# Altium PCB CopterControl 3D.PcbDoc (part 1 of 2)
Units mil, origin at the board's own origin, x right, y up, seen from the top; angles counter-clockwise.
Board outline 1417.32 x 1417.32 mil, 2 copper layers (Top Layer, Bottom Layer), stack 61.2 mil thick; 64 components, 58 nets, 262 pads, 81 vias.
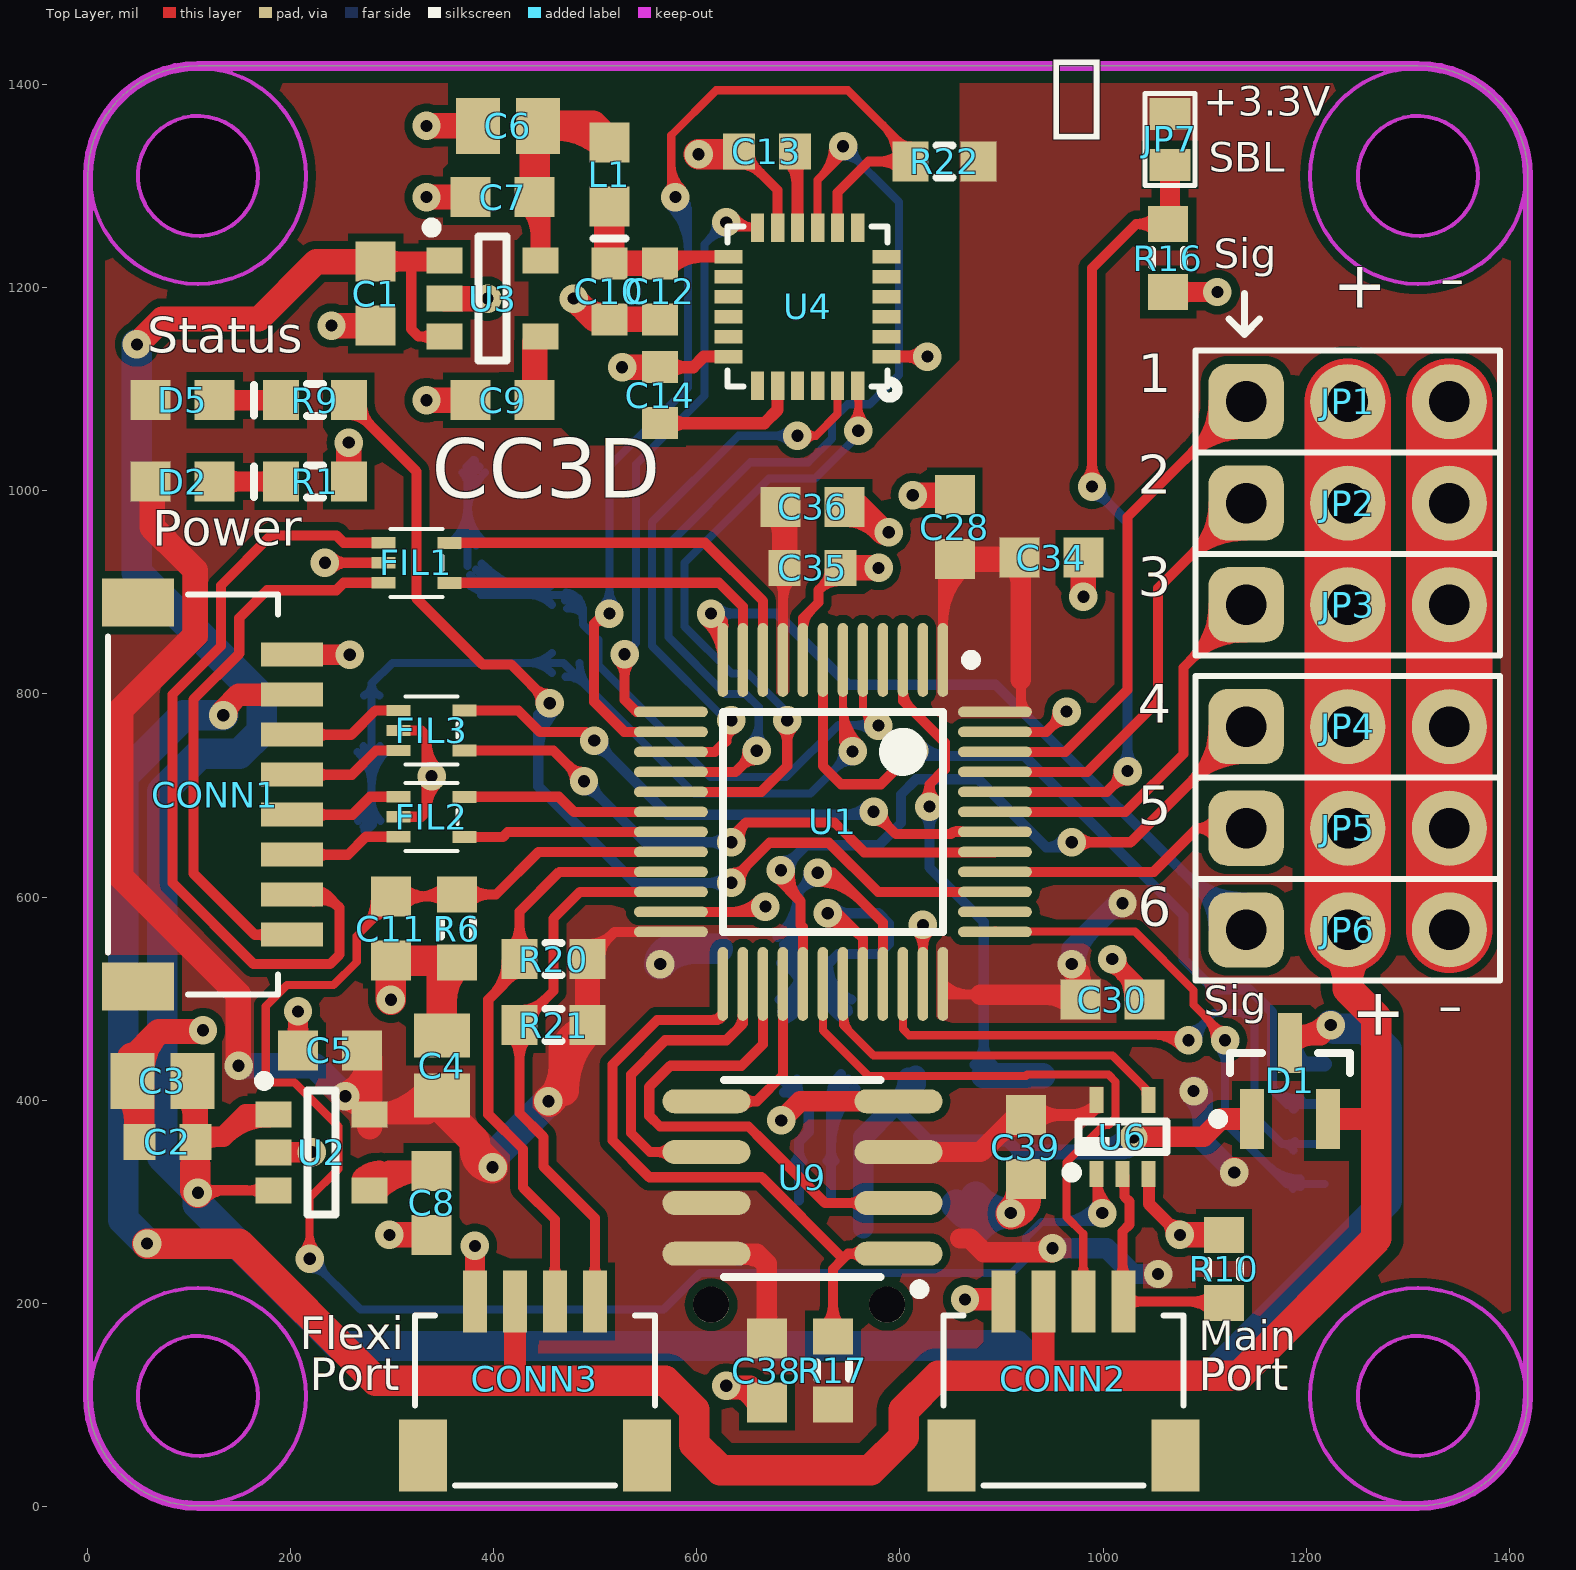
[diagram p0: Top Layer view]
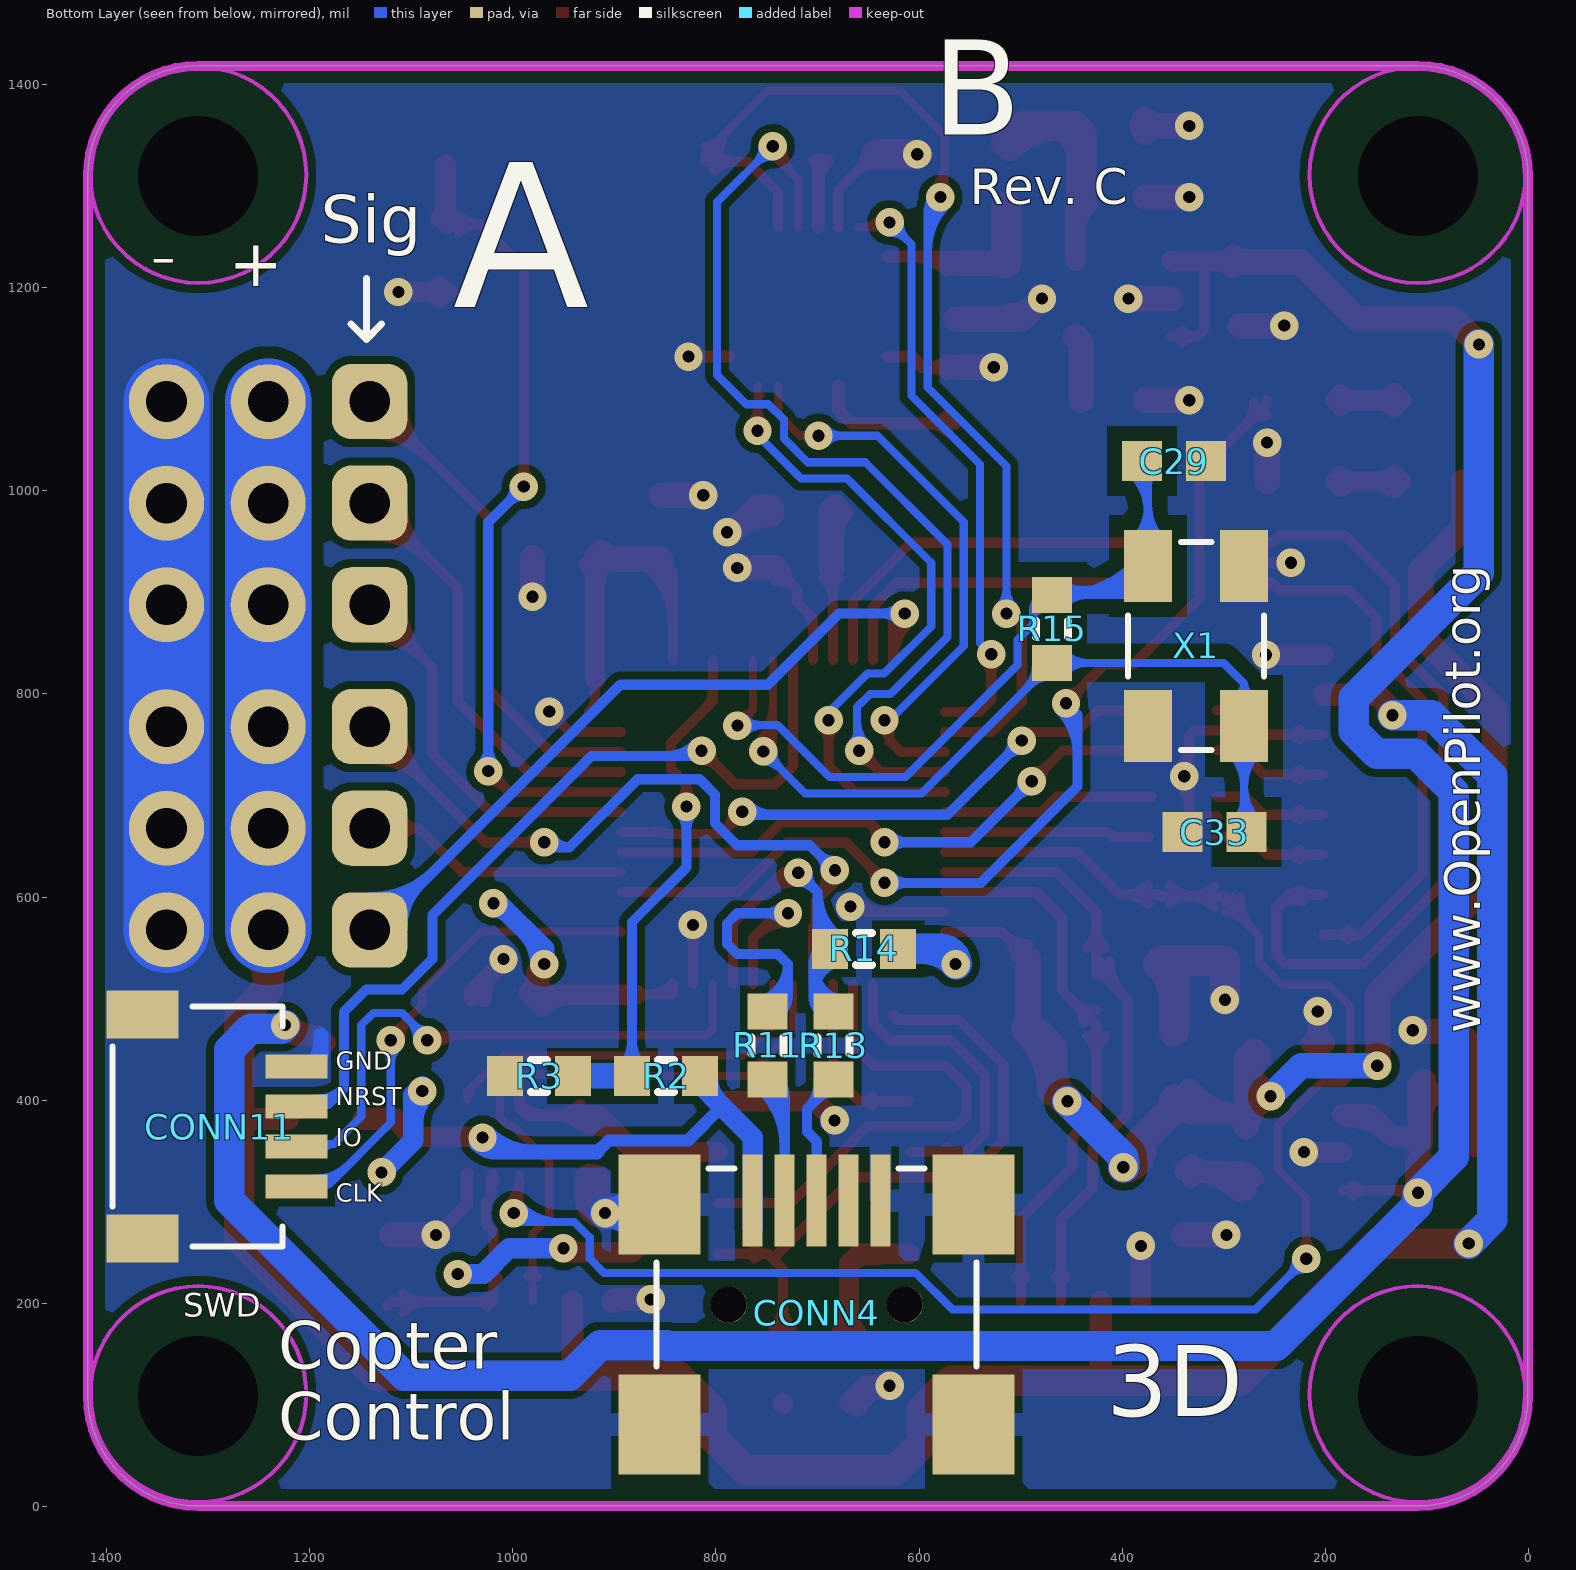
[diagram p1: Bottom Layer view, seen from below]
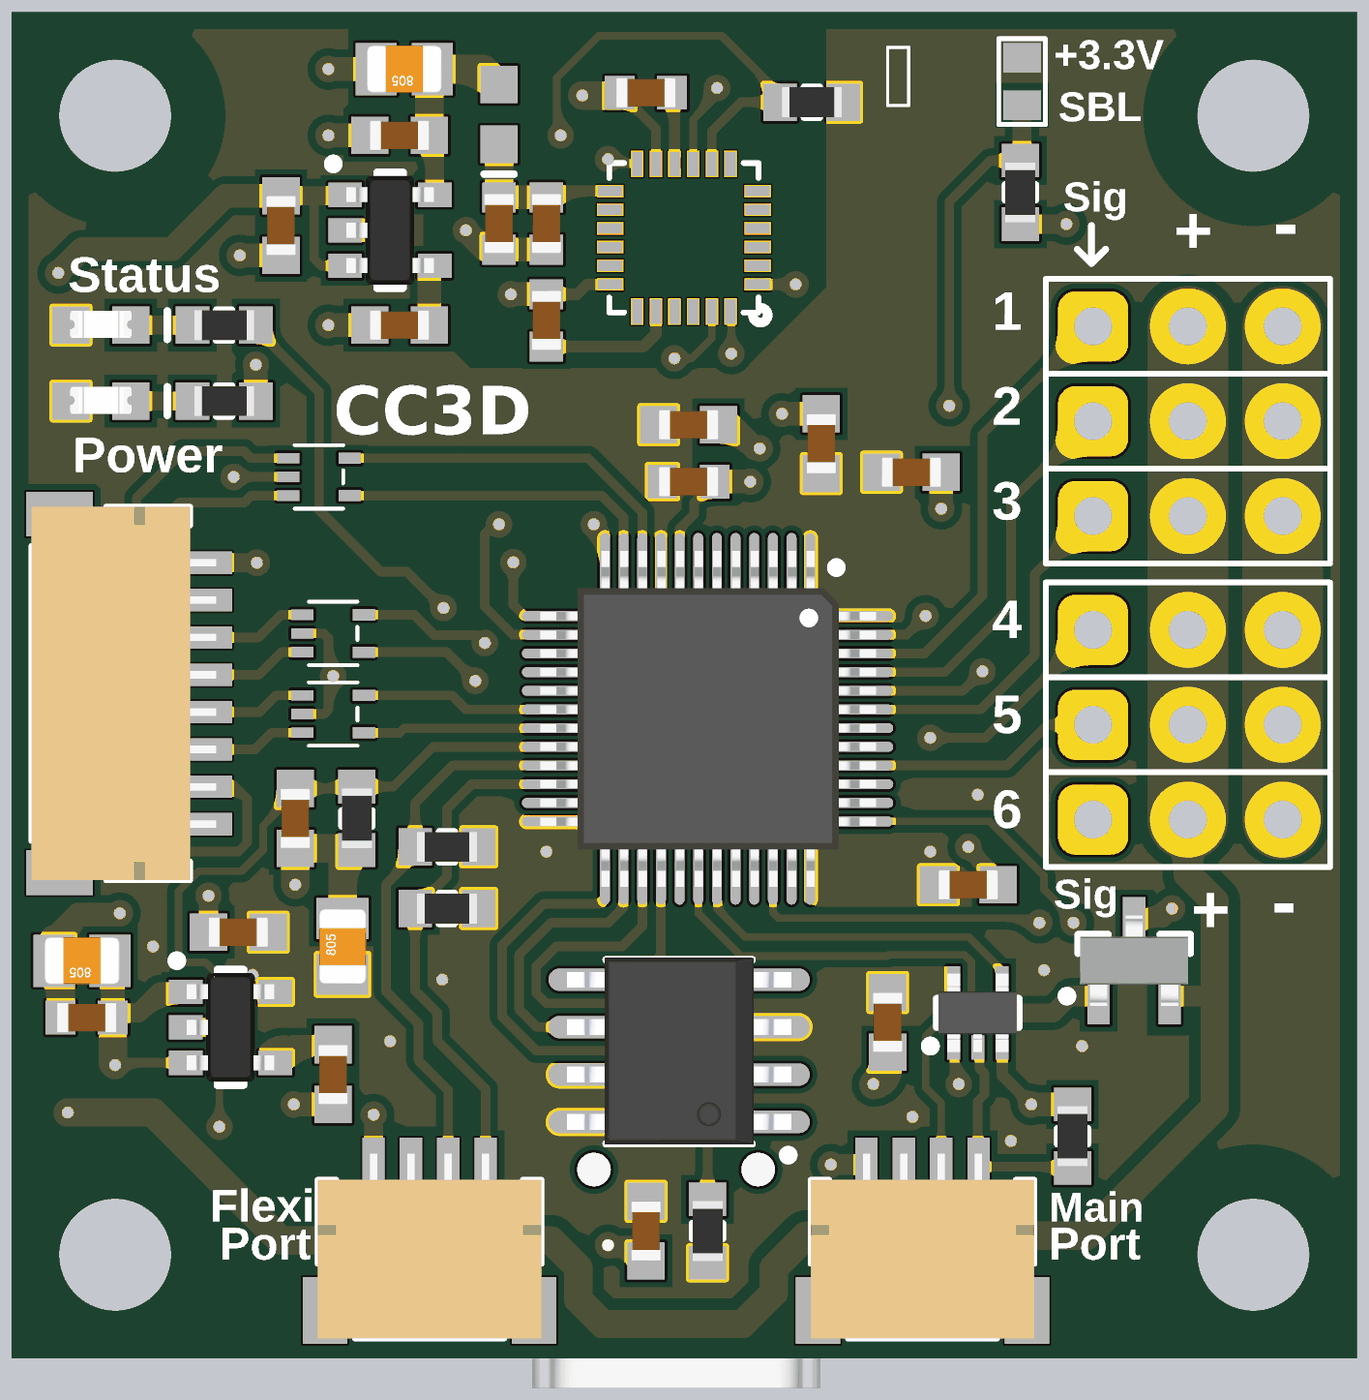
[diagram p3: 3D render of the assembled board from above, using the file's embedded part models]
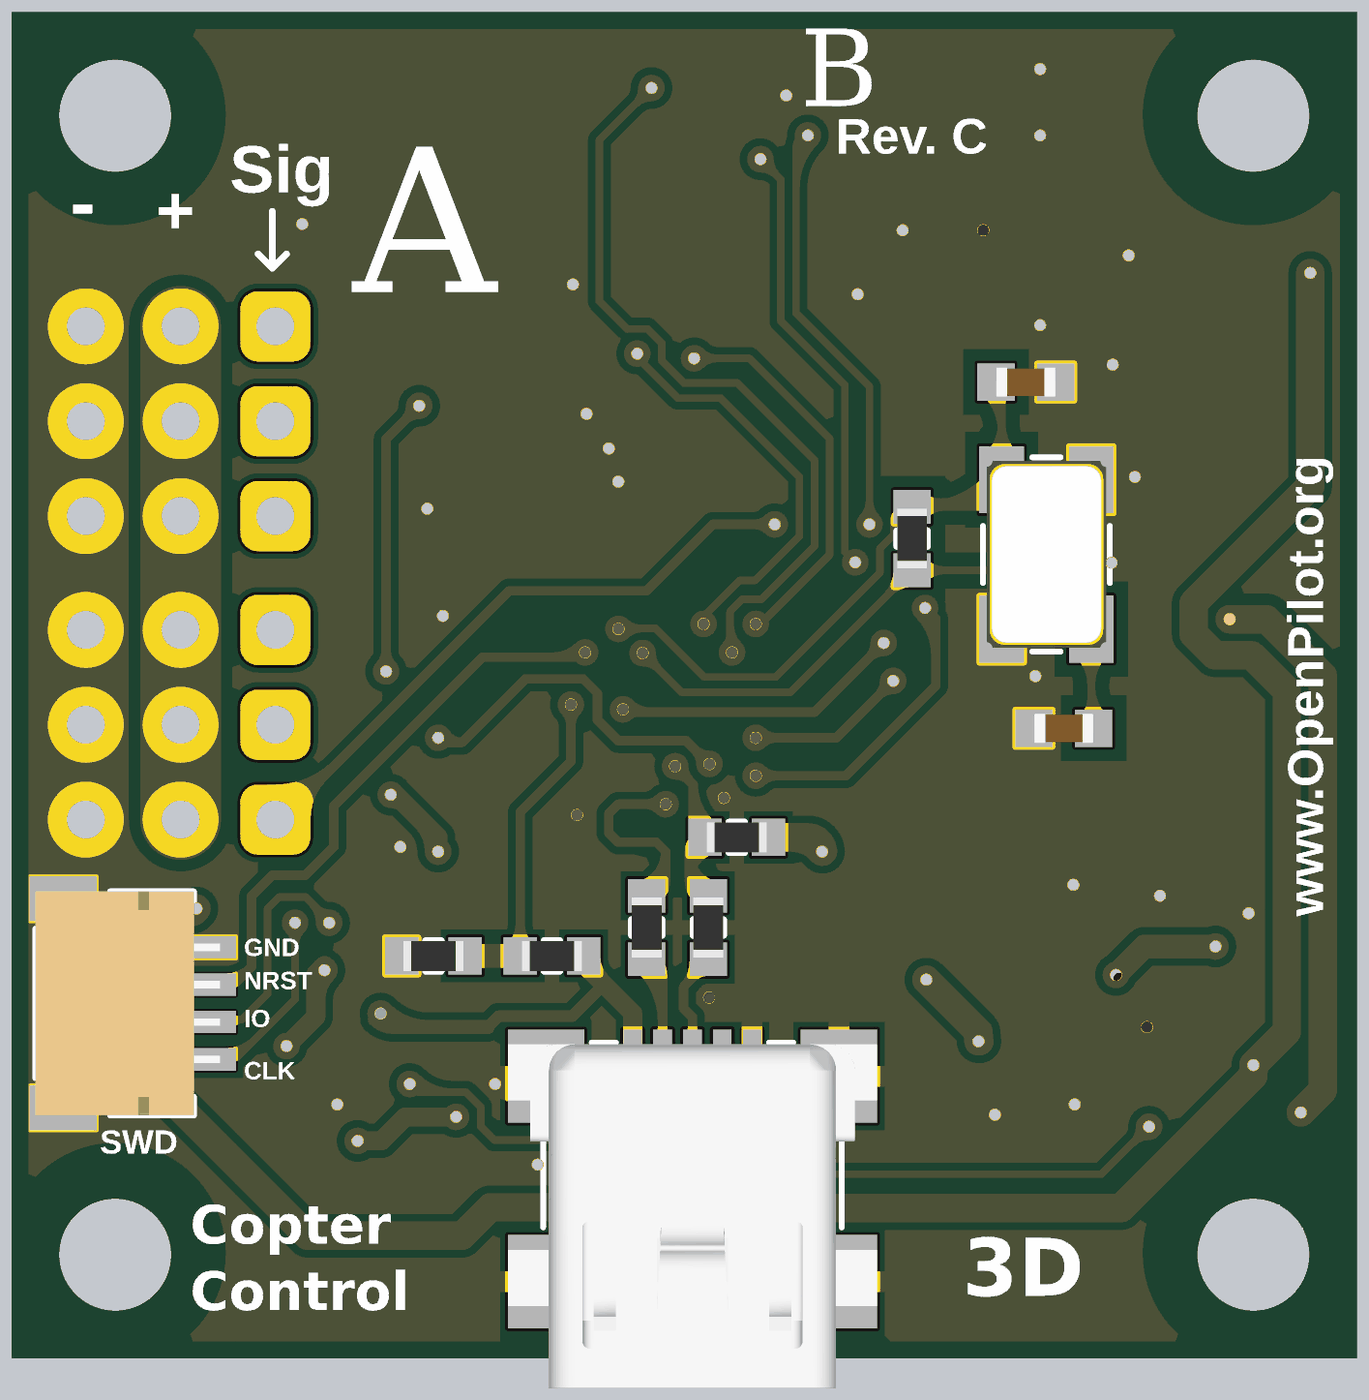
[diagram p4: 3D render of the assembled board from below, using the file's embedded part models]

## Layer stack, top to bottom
Top Layer: signal copper 1.4
Dielectric: core 58.4, FR-4, Dk 4.8
Bottom Layer: signal copper 1.4

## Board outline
0.73,109 ccw(c109,109) 109,0.73 1309.79,0.73 ccw(c1309.79,109) 1418.06,109 1418.06,1309.79 ccw(c1309.79,1309.79) 1309.79,1418.06 109,1418.06 ccw(c109,1309.79) 0.73,1309.79

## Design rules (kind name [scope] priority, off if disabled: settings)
AcuteAngle [All] p1: minimum=6.00000000000000E+0001 checktracksonly=FALSE
Clearance Clearance_osc [InNet('GND') vs InNet('OSC_IN') or InNet('OSC_OUT')] p1: gap=15
Clearance Clearance_outline [All vs OnLayer('Keep-Out Layer')] p2: gap=12
Clearance "VCC_UNREG Pour Clearance" [(InNamedPolygon('Top-VCC') OR InNamedPolygon('Bottom Layer-GND')) vs (InNet('VCC_UNREG'))] p3: gap=12
Clearance "Small Part Clearance" [(HasFootprint('IMU-3000'))] p4: gap=6
Clearance [All] p5: gap=8
ComponentClearance ComponentClearance_servo_headers [InComponent('JP1') or InComponent('JP2') or InComponent('JP3') or InComponent('JP4') or InComponent('JP5') or InComponent('JP6')] p1: gap=5 collisioncheckmode=3 verticalgap=10 showdistances=FALSE
ComponentClearance [All] p2: gap=10 collisioncheckmode=3 verticalgap=10 showdistances=FALSE
DiffPairsRouting [All] p1: maxlimit=20 minlimit=6 mostfreqgap=10 maxuncoupledlength=500
HoleSize [All] p1: absolutevalues=TRUE maxlimit=1000 minlimit=12 maxpercent=80.000 minpercent=20.000
MinimumAnnularRing [All] p1: minimumring=8
MinimumSolderMaskSliver MinimumSolderMaskSliver_FIL1-3 [InComponent('FIL1') or InComponent('FIL2') or InComponent('FIL3')] p1: minsoldermaskwidth=1
MinimumSolderMaskSliver [All] p2: minsoldermaskwidth=3
PlaneClearance [All] p1: clearance=15
PlaneConnect [All] p1: planeconnectstyle=Direct reliefexpansion=20 reliefentries=4 reliefconductorwidth=10 reliefairgap=10
PolygonConnect PolygonConnect_usb [InComponent('CONN4')] p1: connectstyle=Relief reliefconductorwidth=22 reliefentries=4 polygonreliefangle="90 Angle"
PolygonConnect [All] p2: connectstyle=Direct reliefconductorwidth=12 reliefentries=4 polygonreliefangle="90 Angle"
RoutingVias [All] p1: holewidth=15 width=31 viastyle="Through Hole" minholewidth=12 minwidth=28 maxholewidth=28 maxwidth=50
SilkToSilkClearance SilkToSilkClearance_text [IsText] p1: silktosilkclearance=0
SilkToSilkClearance [All] p2: silktosilkclearance=4
SilkscreenOverComponentPads [All] p1: minsilkscreentomaskgap=2
SolderMaskExpansion [All] p1: expansion=3
Width [All] p1: maxlimit=400 minlimit=8 preferedwidth=10
20 further rules are at their usual default settings.

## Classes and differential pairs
differential pair USB_R: +USB_R_P -USB_R_N
differential pair USB_D: +USB_D_P -USB_D_N

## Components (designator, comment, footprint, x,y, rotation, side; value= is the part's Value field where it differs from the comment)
C1 "Cap603" CAP603N 284,1194 r270 top locked
C2 "Cap603" CAP603L 79,359 r180 top locked
C3 "Cap805" CAP805L 74,419 r180 top locked
C4 "Cap805" CAP805L 349,434 r90 top locked
C5 "Cap603" CAP603N 239,449 r180 top locked
C6 "Cap805" CAP805L 414,1359 r180 top locked
C7 "Cap603" CAP603N 409,1289 r180 top locked
C8 "Cap603" CAP603N 339,299 r270 top locked
C9 "Cap603" CAP603N 409,1089 r180 top locked
C10 "Cap603" CAP603L 514,1196.17 r270 top locked
C11 "Cap603" CAP603N 299,569 r270 top locked
C12 "Cap603" CAP603L 564,1196.17 r270 top locked
C13 "Cap603" CAP603L 669,1334 r180 top locked
C14 "Cap603" CAP603L 564,1094 r270 top locked
C28 "Cap603" CAP603N 854,964 r270 top locked
C29 "Cap603" CAP603N 349,1029 r0 bottom locked
C30 "Cap603" CAP603N 1009,499 r180 top locked
C33 "Cap603" CAP603N 309,664 r180 bottom locked
C34 "Cap603" CAP603N 949,934 r180 top locked
C35 "Cap603" CAP603L 714,924 r0 top locked
C36 "Cap603" CAP603N 714,984 r180 top locked
C38 "Cap603" CAP603N 669,134 r270 top locked
C39 "Cap603" CAP603N 924,354 r270 top locked
CONN1 "RC Input" "JST SH 8 Pin Side Entry" 20.73,700.73 r270 top locked
CONN2 "USART 1" "JST SH 4 Pin Side Entry" 960.73,20.73 r0 top locked
CONN3 "Flexi Port" "JST SH 4 Pin Side Entry" 440.73,20.73 r0 top locked
CONN4 "USB" "USB SMD" 700.73,80.73 r180 bottom locked
CONN11 "SWD" "JST SH 4 Pin Side Entry" 1394,374 r270 bottom
D1 "BAT54C" SOT23-3N 1184,419 r90 top locked
D2 "Green" LED603N 94,1009 r180 top locked
D5 "Blue" LED603N 94,1089 r180 top locked
FIL1 "IP4256CZ5-W,115" SOT-665 324,929 r0 top locked
FIL2 "IP4256CZ5-W,115" SOT-665 339,679 r0 top locked
FIL3 "IP4256CZ5-W,115" SOT-665 339,764 r0 top locked
JP1 "Servo out 1" "SIP3 - 0.1" 1140.73,1087.73 r0 top locked
JP2 "Servo out 2" "SIP3 - 0.1" 1140.73,987.73 r0 top locked
JP3 "Servo out 3" "SIP3 - 0.1" 1140.73,887.73 r0 top locked
JP4 "Servo out 4" "SIP3 - 0.1" 1140.73,767.73 r0 top locked
JP5 "Servo out 5" "SIP3 - 0.1" 1140.73,667.73 r0 top locked
JP6 "Servo out 6" "SIP3 - 0.1" 1140.73,567.73 r0 top locked
JP7 "2 PAD Touch JMP" "TOUCH JMP 2PAD" 1065.73,1345.73 r180 top locked
L1 "FB 300mA" IND603N 514,1311.17 r90 top locked
R1 "Res603" RES603N 224,1009 r180 top locked
R2 "Res603" RES603N 849,424 r0 bottom locked
R3 "Res603" RES603N 974,424 r180 bottom locked
R6 "Res603" RES603N 364,569 r90 top locked
R9 "Res603" RES603N 224,1089 r0 top locked
R10 "Res603" RES603N 1119,234 r270 top locked
R11 "Res603" RES603N 749,454 r270 bottom locked
R13 "Res603" RES603N 684,454 r270 bottom locked
R14 "Res603" RES603N 654,549 r0 bottom locked
R15 "Res603" RES603N 469,864 r90 bottom locked
R16 "Res603" RES603N 1064,1229 r90 top locked
R17 "Res603" RES603N 734,134 r90 top locked
R20 "Res603" RES603N 459,539 r0 top locked
R21 "Res603" RES603N 459,474 r0 top locked
R22 "Res603" RES603N 844,1324 r0 top locked
U1 "STM32F103CBT6" "STM32 48 Lead" 734,674 r270 top locked
U2 "LP2992-3.3" SOT23-5L 230.73,348.73 r0 top locked
U3 "LP2992-3.3" SOT23-5L 399,1189 r0 top locked
U4 "MPU-6000" IMU-3000 709,1181.17 r180 top locked
U6 "XOR" DCK-5 1019,364 r90 top locked
U9 "Flash 16Mbits" SOIC8_N 704,324 r180 top locked
X1 "8MHz" "XTAL ACT530SMX-4 Series" 327.27,847.27 r90 bottom locked

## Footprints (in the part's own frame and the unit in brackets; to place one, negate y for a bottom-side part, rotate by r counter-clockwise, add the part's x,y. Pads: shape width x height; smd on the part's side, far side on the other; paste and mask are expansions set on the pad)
CAP603L [mm] "Chip Capacitor, Body 1.6x0.8mm, IPC High Density"
  rect 0.8x0.9 smd: 1(-0.7,0) 2(0.7,0)
  body extent -0.8,-0.4 0.8,0.4, height 0.77
CAP603N [mm] "Chip Capacitor, Body 1.6x0.8mm, IPC Medium Density"
  rect 1x1 smd: 1(-0.8,0) 2(0.8,0)
  body extent -0.8,-0.4 0.8,0.4, height 0.77
CAP805L [mm] "Chip Capacitor, Body 2.0x1.3mm, IPC High Density"
  rect 1.1x1.4 smd: 1(-0.75,0) 2(0.75,0)
  body extent -1,-0.62 1,0.63, height 0.78
DCK-5 [mm] "SOT23-DCK, 5-Leads, Body 2.2x2.4mm (max), Pitch 0.65mm, IPC High Density"
  rect 0.65x0.35 smd mask+0.076: 1(-0.925,0.65) 2(-0.925,0) 3(-0.925,-0.65) 4(0.925,-0.65) 5(0.925,0.65)
  silkscreen extent -0.45,-1.1 0.38,1.1, body extent -1.05,-1.05 1.05,1.05, height 1
IMU-3000 [mm]
  rect 0.711x0.337 smd paste-0.03 mask+0.04: 1(-1.975,1.25) 2(-1.975,0.75) 3(-1.975,0.25) 4(-1.975,-0.25) 5(-1.975,-0.75) 6(-1.975,-1.25) 13(1.975,-1.25) 14(1.975,-0.75) 15(1.975,-0.25) 16(1.975,0.25) 17(1.975,0.75) 18(1.975,1.25)
  rect 0.337x0.711 smd paste-0.03 mask+0.04: 7(-1.25,-1.975) 8(-0.75,-1.975) 9(-0.25,-1.975) 10(0.25,-1.975) 11(0.75,-1.975) 12(1.25,-1.975) 19(1.25,1.975) 20(0.75,1.975) 21(0.25,1.975) 22(-0.25,1.975) 23(-0.75,1.975) 24(-1.25,1.975)
  silkscreen extent -2.25,-2 2,2.27, body extent -2,-2 2,2, height 0.95
IND603N [mm] "Chip Inductor, Body 1.6x0.8mm, IPC Medium Density"
  rect 1x1 smd: 1(-0.8,0) 2(0.8,0)
  silkscreen extent -1.6,-0.4 -1.6,0.4, body extent -0.87,-0.48 0.87,0.48, height 0.71
"JST SH 4 Pin Side Entry" [mm] "SM04B-SRSS-TB"
  rect 1.2x1.8 smd paste+0 mask+0.051: 0(-2.8,0.75) 0(2.8,0.75)
  rect 0.6x1.55 smd paste+0 mask+0.051: 1(-1.5,4.6) 2(-0.5,4.6) 3(0.5,4.6) 4(1.5,4.6)
  silkscreen extent -3,0 3,4.25, body extent -3,0 3,4.95, height 2.92
"JST SH 8 Pin Side Entry" [mm] "SM08B-SRSS-TB"
  rect 1.2x1.8 smd paste+0 mask+0.051: 0(-4.8,0.75) 0(4.8,0.75)
  rect 0.6x1.55 smd paste+0 mask+0.051: 1(-3.5,4.6) 2(-2.5,4.6) 3(-1.5,4.6) 4(-0.5,4.6) 5(0.5,4.6) 6(1.5,4.6) 7(2.5,4.6) 8(3.5,4.6)
  silkscreen extent -5,0 5,4.25, body extent -5,0 5,4.95, height 2.92
LED603N [mm] "Chip LED, Body 1.6x0.8mm, IPC Medium Density"
  rect 1x1 smd: 1(-0.8,0) 2(0.8,0)
  silkscreen extent -1.78,-0.38 -1.78,0.38, body extent -0.82,-0.38 0.82,0.34, height 0.68
RES603N [mm] "Chip Resistor, Body 1.6x0.8mm, IPC Medium Density"
  rect 0.9x1 smd: 1(-0.85,0) 2(0.85,0)
  silkscreen extent -0.2,-0.4 0.2,0.4, body extent -0.8,-0.4 0.8,0.4, height 0.44
"SIP3 - 0.1" [mil] "Standard 0.1 3 Pin Header"
  rrect50% 74x74 hole 40: 1(0,0)
  round 74 hole 40: 2(100,0) 3(200,0)
  silkscreen extent -50,-50 250,50, body extent -47,-47 248,47, height 394
SOIC8_N [mm] "8-Pin Small Outline Integrated Circuit Package (SOIC8), IPC Medium Density"
  oval 2.2x0.6 smd: 1(-2.4,1.905) 2(-2.4,0.635) 3(-2.4,-0.635) 4(-2.4,-1.905) 5(2.4,-1.905) 6(2.4,-0.635) 7(2.4,0.635) 8(2.4,1.905)
  silkscreen extent -3.05,-2.44 1.96,2.92, body extent -3.01,-2.5 3.01,2.5, height 1.75
SOT23-3N [mm] "SOT23, 3-Leads, Body 2.9x1.3mm, Pitch 0.95mm, Lead Span 2.5mm, IPC Medium Density"
  rect 1.5x0.6 smd: 1(-0.95,0.95) 2(-0.95,-0.95) 3(0.95,0)
  silkscreen extent -1.07,-1.5 0.7,1.92, body extent -1.21,-1.45 1.21,1.45, height 0.99
SOT23-5L [mm] "SOT23, 5-Leads, Body 2.9x1.6mm, Pitch 0.95mm, Lead Span 2.8mm, IPC High Density"
  rect 0.9x0.65 smd mask+0.076: 1(-1.2,0.95) 2(-1.2,0) 3(-1.2,-0.95) 4(1.2,-0.95) 5(1.2,0.95)
  silkscreen extent -1.56,-1.55 0.35,1.91, body extent -1.17,-1.46 1.17,1.46, height 0.97
SOT-665 [mm] "NXP SOT665"
  rect 0.6x0.28 smd mask+0.076: 1(-0.825,0.5) 2(-0.825,0) 3(-0.825,-0.5)
  rect 0.6x0.3 smd mask+0.076: 4(0.825,-0.5) 5(0.825,0.5)
  silkscreen extent -0.65,-0.85 0.65,0.85, body extent -0.65,-0.85 0.65,0.85, height 0.6
"STM32 48 Lead" [mm] "Thin QFP, 48-Leads, Body 7x7mm, Pitch 0.5mm, IPC Medium Density"
  oval 1.85x0.265 smd mask+0.076: 1(-4.05,2.75) 2(-4.05,2.25) 3(-4.05,1.75) 4(-4.05,1.25) 5(-4.05,0.75) 6(-4.05,0.25) 7(-4.05,-0.25) 8(-4.05,-0.75) 9(-4.05,-1.25) 10(-4.05,-1.75) 11(-4.05,-2.25) 12(-4.05,-2.75) 25(4.05,-2.75) 26(4.05,-2.25) 27(4.05,-1.75) 28(4.05,-1.25) 29(4.05,-0.75) 30(4.05,-0.25) 31(4.05,0.25) 32(4.05,0.75) 33(4.05,1.25) 34(4.05,1.75) 35(4.05,2.25) 36(4.05,2.75)
  oval 0.265x1.85 smd mask+0.076: 13(-2.75,-4.05) 14(-2.25,-4.05) 15(-1.75,-4.05) 16(-1.25,-4.05) 17(-0.75,-4.05) 18(-0.25,-4.05) 19(0.25,-4.05) 20(0.75,-4.05) 21(1.25,-4.05) 22(1.75,-4.05) 23(2.25,-4.05) 24(2.75,-4.05) 37(2.75,4.05) 38(2.25,4.05) 39(1.75,4.05) 40(1.25,4.05) 41(0.75,4.05) 42(0.25,4.05) 43(-0.25,4.05) 44(-0.75,4.05) 45(-1.25,4.05) 46(-1.75,4.05) 47(-2.25,4.05) 48(-2.75,4.05)
  silkscreen extent -4.17,-2.75 2.75,3.58, body extent -4.5,-4.49 4.5,4.51, height 1.56
"TOUCH JMP 2PAD" [mil] "Touch Jumper 2 Pad"
  rect 40x31.5 smd mask+0: 1(0,25) 2(0,-25)
  silkscreen extent -25,-45 25,45
"USB SMD" [mm] "DX2R005HN2E700"
  rect 2.05x2.5 smd: 0(-3.925,0) 0(-3.925,5.5) 0(3.925,0) 0(3.925,5.5)
  rect 0.5x2.3 smd mask+0.085: 1(-1.6,5.6) 2(-0.8,5.6) 3(0,5.6) 4(0.8,5.6) 5(1.6,5.6)
  round 0.9 hole 0.9 unplated: 6(-2.2,3) 6(2.2,3)
  silkscreen extent -4,1.45 4,6.4, body extent -4.95,-2.85 4.95,6.35, height 4.17
"XTAL ACT530SMX-4 Series" [mm] "ACT530SMX-4Series from ACT"
  rect 1.8x1.2 smd: 1(-2,-1.2) 2(2,-1.2) 3(2,1.2) 4(-2,1.2)
  silkscreen extent -2.6,-1.7 2.6,1.7, body extent -2.5,-1.6 2.5,1.6, height 1

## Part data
C1 C2 C3 C4 C5 C6 C7 C8 C9 C10 C11 C12 C13 C14 C28 C29 C30 C33 C34 C35 C36 C38 C39: "Capacitor SMD"
CONN1: library part "JST-SH 8-pin Side Entry Socket", "JST-SH 8-pin Side Entry Socket"
CONN2 CONN3 CONN11: library part "JST-SH 4-pin Side Entry Socket", "JST-SH 4-pin Side Entry Socket"
CONN4: library part USB_SMT_B, "USB Type-B SMT Socket"
D1: "Dual Diode Command Cathode"
D2: library part "LED 603 Gr", "Green 603 LED"
D5: library part "LED 603 Bl", "Blue 603 LED"
FIL1 FIL2 FIL3: library part "RF Filter 100R 30pF", "IP4256CZ5-W,115 2 channel, 100R, 30pF, RF ESD Filter"
JP1 JP2 JP3 JP4 JP5 JP6: library part "Hdr 3 Pin 0.1", "Header, 3-Pin, 0.1\""
JP7: "2 Pad Touch Jumper"
L1: library part FerriteBead_300mA, "Ferrite Bead 300mA"
R1 R2 R3 R6 R9 R10 R11 R13 R14 R15 R16 R17 R20 R21 R22: "Resistor SMD"
U1: "STM32 ARM-based 32-bit MCU with 128 Kbytes Flash, 48-pin LQFP, Industrial Temperature"
U2 U3: library part LP2985-3.3, "3.3V 250mA LDO Regulator"
U4: library part MPU-3/6000, "Invensense MPU-3/6000,  3-axis Gyros & Accel on 6000"
U6: library part "XOR SN74LVC1G86DCKR", "XOR Gate SN74LVC1G86DCKR"
U9: library part "Flash 16Mb 75MHZ 8SOIC", "16Mbit SPI Flash Memory"
X1: library part "XTAL ACT530SMX-4", "Surface Mount Quartz Crystal, Digikey 535-9720-1-ND"

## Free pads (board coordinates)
  round 0 hole 118.11 unplated: 0(109,109) 0(109,1309.79) 0(1309.79,109) 0(1309.79,1309.79)

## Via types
v1: diameter 28, hole 12, Top Layer to Bottom Layer, tented both sides, 81 vias

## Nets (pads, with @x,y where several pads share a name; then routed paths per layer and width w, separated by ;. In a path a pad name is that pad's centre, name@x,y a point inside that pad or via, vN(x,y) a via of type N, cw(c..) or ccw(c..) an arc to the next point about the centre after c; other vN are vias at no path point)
BOOT: JP7.1 R16.2 U1.44 | length 1011.8
  Top Layer w10: U1.44@893.45,703.53 1003.53,703.53 v1(1024,724) ; v1@982.64,1010.36 ccw(c967.27,1025.73) 989,1025.73 ccw(c1010.73,1025.73) v1@995.36,1010.36 ; v1(989,1004) 989,1219 1032.47,1262.47 ; v1@1015,724 cw(c993.27,724) 1008.64,708.64 cw(c1024,693.27) v1@1024,715 ; R16.2@1052.8,1253.72 ccw(c1032.47,1234.46) 1032.47,1262.47 ; R16.2@1052.8,1271.21 cw(c1032.47,1290.47) 1032.47,1262.46 ; R16.2@1064,1262.47 1032.47,1262.47
  Top Layer w20: R16.2@1060.51,1267.92 ccw(c1047.91,1280.53) 1065.73,1280.53 ; R16.2@1064,1262.47 1065.73,1264.2 JP7.1@1065.73,1320.73 ; 1065.73,1281.66 ccw(c1085.17,1281.66) R16.2@1071.42,1267.92
  Bottom Layer w10: v1@989,995 cw(c989,973.27) 1004.36,988.64 cw(c1019.73,1004) v1@998,1004 ; v1(989,1004) 1024,969 v1(1024,724) ; v1@1017.64,730.36 ccw(c1002.27,745.73) 1024,745.73 ccw(c1045.73,745.73) v1@1030.36,730.36
CS_FLSH: R17.2 U1.25 U9.1 | length 708.6
  Top Layer w10: 614.71,479 ccw(c614.71,494.38) U1.25@625.58,483.5 ; U1.25@624,484 619,479 ; U1.25@625.53,483.43 cw(c619,486.03) 619,479 ; R17.2@725.01,176.46 ccw(c703.3,198.17) 734,198.17 ccw(c764.7,198.17) R17.2@742.99,176.46 ; R17.2@734,167.47 734,234 744,244 ; U9.1@762.18,244.18 ccw(c750.55,232.56) 750.55,249 ccw(c750.55,265.44) U9.1@762.18,253.82 ; U9.1@798.49,249 749,249 744,244 ; 619,479 561,479 517.2,435.2 517.2,360.34 553.36,324.19 663.81,324.19 744,244
GND: C1.2 C2.2 C3.2 C4.2 C5.2 C6.2 C7.2 C8.2 C9.2 C10.2 C11.2 C12.2 C13.2 C14.1 C28.1 C29.1 C30.1 C33.1 C34.1 C35.2 C36.1 C38.2 C39.2 CONN1.1 CONN2.1 CONN3.1 CONN4.0 CONN4.5 CONN11.0 CONN11.1 FIL1.2 FIL2.2 FIL3.2 JP1.3 JP2.3 JP3.3 JP4.3 JP5.3 JP6.3 R1.1 R3.1 R6.1 R10.1 R16.1 U1.8 U1.23 U1.35 U1.47 U2.2 U3.2 U4.1 U4.11 U4.18 U6.3 U9.4 X1.2 X1.4 | length 4595.5
  Top Layer w10: v1(234,929) FIL1.2@291.52,929 ; v1@240.36,922.64 cw(c255.73,907.27) 255.73,929 cw(c255.73,950.73) v1@240.36,935.36 ; FIL2.2@306.52,679 329,679 334,684 v1@334,719 ; FIL3.2@306.52,764 329,764 334,759 v1@334,719 ; 334,685.2 cw(c372.8,685.2) v1@345.36,712.64 ; 334,752.8 ccw(c372.8,752.8) v1@345.36,725.36 ; v1(339,719) v1@334,719 ; U1.23@574.55,585.42 662.32,585.42 v1(667.58,590.68) ; 633.14,585.42 ccw(c633.14,625.13) v1@661.22,597.05 ; C13.2@641.44,1321.28 cw(c641.44,1290.58) 663.15,1312.29 ; C13.2@641.44,1334 679.47,1295.97 U4.11@679.47,1258.92 ; C13.2@652.19,1332.03 ccw(c673.38,1332.03) 658.4,1317.04 ; U1.8@704.47,833.45 704.47,874.47 719.87,889.87 719.87,902.31 ; U1.8@704.69,864.65 cw(c728.92,864.65) 711.79,881.79 ; 724.6,907.04 ccw(c709.62,922.03) C35.2@730.81,922.03 ; C35.2@741.55,911.28 ccw(c741.53,880.64) 719.87,902.31 ; C35.2@741.56,924 719.87,902.31 ; v1@816.22,566.22 cw(c800.86,550.86) 822.58,550.86 cw(c844.31,550.86) v1@828.95,566.22 ; U1.35@822.58,514.55 v1(822.58,572.58) ; U1.47@893.45,762.58 944.08,762.58 v1(964,782.5) ; v1@955,782.5 cw(c933.27,782.5) 948.64,767.14 cw(c964,751.77) v1@964,773.5
  Top Layer w12: C14.1@564,1121.56 596.56,1121.56 606.95,1131.95 U4.18@631.24,1131.95 ; C14.1@572.86,1114.67 cw(c589.5,1098.02) 589.5,1121.56 cw(c589.5,1145.09) C14.1@572.86,1128.45 ; U4.1@786.76,1131.95 v1(826.95,1131.95) ; v1@821.3,1126.3 ccw(c807.64,1112.64) 807.64,1131.95 ccw(c807.64,1151.27) v1@821.3,1137.61 ; U6.3@1044.59,327.58 1045,327.17 1045,298 v1(1075.54,267.46) ; v1@1067.54,267.46 ccw(c1048.22,267.46) 1061.88,281.12 ccw(c1075.54,294.78) v1@1075.54,275.46
  Top Layer w15: v1@1007.32,532.72 cw(c1001.74,511.91) 1020.4,522.68 ; v1@1009,532.5 cw(c1009,516.81) 1020.1,527.9 cw(c1031.19,539) v1@1015.5,539 ; v1(1009,539) 1040.5,507.5 C30.1@1040.5,499 ; v1@1013.68,534.32 cw(c978.37,499) C30.1@1028.31,499
  Top Layer w20: U2.2@183.49,348.73 223.73,348.73 223.47,349 v1(221.23,349) ; C5.2@200.65,455.85 ccw(c184.12,472.38) 207.5,472.38 ccw(c230.88,472.38) C5.2@214.35,455.85 ; CONN1.1@201.84,838.53 v1(258.53,838.53) ; C5.2@207.5,449 v1(207.5,487.5) ; CONN3.1@381.68,201.84 v1(381.68,256.68) ; v1@629.67,115.06 cw(c637.17,70.68) C38.2@669,102.5 652.5,119 v1(629,119) cw(c629,85.04) C38.2@660.12,98.63 ; v1(683.14,380.14) 702,399 U9.4@798.49,399 ; R16.1@1064,1195.53 v1(1112.47,1195.53) ; R16.1@1071.42,1190.08 cw(c1084.6,1176.91) 1084.6,1195.53 cw(c1084.6,1214.16) R16.1@1071.42,1200.99
  Top Layer w22: v1(864,204) 899.51,204 CONN2.1@901.68,201.84
  Top Layer w25: C3.2@44.47,441.69 70.42,467.63 ; C3.2@53.62,425.2 cw(c111.04,427.01) 70.42,467.63 ; v1(114,469) 112.63,467.63 70.42,467.63 ; v1(240.5,1162.5) C1.2@284,1162.5 ; R1.1@257.47,1009 v1(257.47,1047.28) ; v1(297.5,267.5) C8.2@339,267.5 ; v1(334,1089) C9.2@377.5,1089 ; v1(334,1289) C7.2@377.5,1289 ; v1(334,1359) C6.2@380.53,1359 ; U3.2@351.76,1189 v1(394,1189) ; C6.2@378,1352.53 ccw(c362.37,1336.9) 362.37,1359 ccw(c362.38,1381.1) C6.2@378,1365.47 ; v1(479,1189) 499.39,1168.61 C10.2@514,1168.61 C12.2@564,1168.61 ; v1@484.91,1183.09 ccw(c512.03,1210.2) C10.2@512.03,1171.85 ; v1(526.44,1121.56) C14.1@564,1121.56 ; C35.2@741.56,924 v1(779,924) ; C36.1@745.5,976.82 cw(c745.5,926.87) v1@780.81,962.19 ; C36.1@745.5,984 759,984 784,959 v1(789,959) ; v1(812.5,995.5) C28.1@854,995.5 ; v1(980.5,895.5) C34.1@980.5,934 ; v1(1075.54,267.46) R10.1@1119,267.46
  Top Layer w30: C3.2@39.77,408.39 cw(c11.59,380.21) 51.44,380.21 ; C3.2@44.47,441.69 C3.2@44.47,419 51.44,412.03 C2.2@51.44,359 ; v1(299,499) C11.2@299,537.5 362.03,537.5 R6.1@364,535.54 349,520.54 C4.2@349,467.46 ; 349,497.52 cw(c400.05,497.52) R6.1@363.95,533.61 ; v1(601.84,1331.16) C13.2@641.44,1331.16 ; v1@909.07,288 ccw(c907.96,304) C39.2@924,304 ; v1@909.7,288.29 ccw(c875.92,322.5) C39.2@924,322.5 C39.2@924,304 ; C39.2@919.38,321.71 cw(c882.63,315.38) v1(909,289) C39.2@924,304
  Top Layer w50: JP1.3@1340.73,1087.73 JP1.3@1340.73,1094.51
  Top Layer w85: JP6.3@1340.73,567.73 JP5.3@1340.73,667.73 JP4.3@1340.73,767.73 JP3.3@1340.73,887.73 JP2.3@1340.73,987.73 JP1.3@1340.73,1087.73
  Bottom Layer w10: v1(667.58,590.68) v1@669,589.27 ; v1@679,376 v1(683.14,380.14)
  Bottom Layer w15: 1189,456.01 ccw(c1217.15,456.01) CONN11.1@1197.25,436.1 ; 1189,464 1189,444 1197.21,435.79 CONN11.1@1217.9,435.79
  Bottom Layer w30: CONN4.0@855.26,297.27 863.53,289 v1(909,289) ; CONN4.0@874.53,304.88 ccw(c909,334.33) v1(909,289) ; CONN4.0@875.11,272.64 cw(c909,245.73) v1(909,289)
  Bottom Layer w35: JP6.3@1340.73,560.73 JP6.3@1340.73,567.73
  Bottom Layer w85: JP6.3@1340.73,567.73 JP5.3@1340.73,667.73 JP4.3@1340.73,767.73 JP3.3@1340.73,887.73 JP2.3@1340.73,987.73 JP1.3@1340.73,1087.73
GYRO_CS#: R22.1 U1.14 U4.8 | length 1434.6
  Top Layer w8: v1@571.93,1296.07 ccw(c564.91,1303.09) 574.84,1303.09 ; 574.84,1303.88 ccw(c593.88,1303.88) v1@580.41,1290.41 ; 574.84,1323.2 ccw(c613.2,1323.2) v1@586.07,1296.07 ; v1(579,1289) 574.84,1293.16 574.84,1349.84 619.06,1394.06 748.94,1394.06 810.54,1332.46 R22.1@810.54,1324 ; 782.53,1360.47 cw(c748.02,1325.97) R22.1@796.82,1325.97 ; 796.18,1346.82 cw(c775.34,1325.97) R22.1@804.82,1325.97 ; 798.21,1344.79 ccw(c810.54,1357.12) R22.1@810.54,1339.68
  Top Layer w10: v1@509,879 499,869 ; v1@510.1,870.89 ccw(c505.88,862.12) 499,869 ; U1.14@574.55,762.58 528.6,762.58 499,792.18 499,869 ; U4.8@739,1259.39 U4.8@738.53,1258.92 738.53,1293.53 769,1324 R22.1@810.54,1324 ; R22.1@801.54,1315.01 ccw(c779.84,1293.3) 779.84,1324 ccw(c779.84,1354.7) R22.1@801.54,1332.99
  Bottom Layer w8: v1@506.93,886.07 ccw(c489.86,903.14) 514,903.14 ccw(c538.14,903.14) v1@521.07,886.07 ; v1(514,879) 514,1024 591.5,1101.5 591.5,1276.5 v1(579,1289) ; v1@571.93,1281.93 cw(c524.68,1234.68) 591.5,1234.68 ; v1@577.59,1287.59 cw(c543.99,1253.99) 591.5,1253.99 ; v1@583.24,1293.24 cw(c563.31,1273.31) 591.5,1273.31
GYRO_INT#: U1.13 U4.12 | length 713.4
  Top Layer w8: v1(629,1264) 634.08,1258.92 U4.12@659.79,1258.92 cw(c659.79,1287.89) v1@636.9,1270.13 ; v1@630.58,1265.23 ccw(c643.45,1275.21) 643.45,1258.92
  Top Layer w10: v1@522.64,832.64 cw(c507.27,817.27) 529,817.27 cw(c550.73,817.27) v1@535.36,832.64 ; v1(529,839) 529,794 540.73,782.27 U1.13@574.55,782.27 ; 538.51,784.49 ccw(c543.35,789.33) U1.13@543.35,782.48
  Bottom Layer w8: v1(529,839) 540,850 540,1025.96 607.5,1093.46 607.5,1242.5 v1(629,1264) ; v1@619,1264 cw(c594.86,1264) 611.93,1246.93 cw(c629,1229.86) v1@629,1254
GYRO_VDD: C10.1 C12.1 L1.1 U4.13 | length 212.3
  Top Layer w12: C12.1@564,1223.72 570.66,1230.38 U4.13@631.24,1230.38 ; C12.1@572.86,1216.83 cw(c605.57,1184.12) 605.57,1230.38
  Top Layer w25: C10.1@514,1223.73 C12.1@564,1223.72
  Top Layer w30: C10.1@514,1223.73 L1.1@514,1279.67
INV: C11.1 R6.2 U1.20 U6.1 | length 2129.8
  Top Layer w8: v1@211.93,251.07 ccw(c194.86,268.14) 219,268.14 ccw(c243.14,268.14) v1@226.07,251.07 ; v1(219,244) 219,304 247.23,332.23 247.23,374 203.92,417.31 182.85,417.31 175.82,424.34 175.82,492.59 196.73,513.5 242.54,513.5 265.31,536.27 265.31,561.57 C11.1@299,595.26 ; 268.52,564.78 ccw(c232.8,600.5) C11.1@283.31,600.5 ; 281.16,577.42 cw(c299,559.59) C11.1@299,584.81 ; 282.18,578.44 ccw(c260.12,600.5) C11.1@291.31,600.5 ; U6.1@991.37,319.63 cw(c986.43,314.7) 993.41,314.7 cw(c1000.39,314.7) U6.1@995.45,319.63 ; 993.41,307.33 ccw(c1017.33,307.33) v1@1000.41,290.41 ; U6.1@993.41,326.64 ccw(c1036.64,326.64) v1@1006.07,296.07 ; U6.1@993.41,327.58 993.41,284.59 994,284 v1(999,289)
  Top Layer w10: C11.1@299,595.26 C11.1@299,600.5 362.03,600.5 R6.2@364,602.47 402.47,602.47 444.47,644.47 U1.20@574.55,644.47 ; C11.1@309.38,590.11 cw(c334.45,565.04) 334.45,600.5 cw(c334.45,635.95) C11.1@309.38,610.88 ; 326.57,600.5 ccw(c326.57,637.92) R6.2@353.04,611.46 ; 336.09,600.5 cw(c336.09,576.52) R6.2@353.04,593.47 ; R6.2@374.96,593.47 cw(c396.67,571.76) 396.67,602.47 cw(c396.67,633.17) R6.2@374.96,611.46
  Bottom Layer w8: v1@219,234 cw(c219,209.86) 236.07,226.93 cw(c253.14,244) v1@229,244 ; v1(219,244) 269,194 567.25,194 603.25,230 910,230 924.11,244.11 924.11,265.12 939.34,280.35 990.35,280.35 v1(999,289) ; 953.97,280.35 ccw(c953.97,334.03) v1@991.93,296.07 ; 973.28,280.35 ccw(c973.28,314.72) v1@997.59,290.41
LED_BLUE: R9.2 U1.39 | length 1250.2
  Top Layer w10: R9.2@257.47,1074.32 cw(c257.47,1047.23) 276.62,1066.38 ; R9.2@257.47,1089 257.47,1085.53 324,1019 324,894 389,829 417.18,829 v1(455.37,790.82) ; R9.2@270.18,1087.03 ccw(c304.5,1087.03) 280.23,1062.77 ; v1@446.37,790.82 ccw(c424.64,790.82) 440,806.18 ccw(c455.37,821.55) v1@455.37,799.82 ; v1@634,623 ccw(c634,640.34) 646.26,628.08 ; v1@643,614 cw(c669.11,614) 650.65,632.46 ; U1.39@893.45,605.1 778.35,605.1 730.05,653.41 671.59,653.41 655.77,637.59 642.18,624 v1@639,624 ; v1@639,624 v1(634,614) 634,620.82 637.18,624 v1@639,624
  Bottom Layer w10: 444,741.65 cw(c504.53,741.65) v1@461.73,784.45 ; 444,765.79 cw(c480.39,765.79) v1@454.66,791.53 ; v1(455.37,790.82) 444,779.45 444,709 539,614 v1(634,614) ; v1@627.64,607.64 ccw(c612.27,592.27) 612.27,614 ccw(c612.27,635.73) v1@627.64,620.36
MISO: U1.16 U4.9 | length 1153.9
  Top Layer w8: U4.9@718.84,1258.92 718.84,1305.85 744,1331 v1(744,1339) ; 721.28,1308.28 ccw(c690.56,1339) v1@734,1339 ; 734.93,1321.94 ccw(c717.87,1339) v1@742,1339
  Top Layer w10: U1.16@574.55,723.21 638.21,723.21 v1(659,744) ; v1@650,744 cw(c628.27,744) 643.64,728.64 cw(c659,713.27) v1@659,735
  Bottom Layer w8: v1@651.93,751.07 ccw(c630.03,772.97) 661,772.97 ; v1@661,746 661,787 648,800 628,800 572,856 572,947 653,1028 709.77,1028 733,1051.23 733,1069.77 748.23,1085 769.77,1085 769.88,1084.88 799,1114 799,1284 v1(744,1339) ; 661,763.31 ccw(c678.31,763.31) v1@666.07,751.07 ; v1@744,1329 cw(c744,1304.86) 761.07,1321.93 cw(c778.14,1339) v1@754,1339
  Bottom Layer w10: v1(659,744) v1@661,746
MOSI: U1.17 U4.24 | length 727.6
  Top Layer w8: v1@751.93,1066.07 ccw(c734.86,1083.14) 759,1083.14 ccw(c783.14,1083.14) v1@766.07,1066.07 ; U4.24@756.36,1094.18 cw(c749.98,1087.8) 759,1087.8 ; U4.24@758.21,1103.41 759,1102.62 v1(759,1059)
  Top Layer w10: U1.17@574.55,703.53 663.53,703.53 689,729 v1(689,774) ; v1@682.64,767.64 cw(c667.27,752.27) 689,752.27 cw(c710.73,752.27) v1@695.36,767.64
  Bottom Layer w8: v1(689,774) 689,781.63 650.63,820 634.44,820 588,866.44 588,929 671,1012 716.4,1012 759,1054.6 v1(759,1059)
NetC8_1: C8.1 U2.4 | length 195.8
  Top Layer w20: U2.4@270.73,323.5 cw(c287.63,306.6) 287.63,330.5 ; U2.4@277.98,311.33 297.14,330.5 C8.1@339,330.5 ; U2.4@284.87,309.36 cw(c335.91,258.32) C8.1@335.91,330.5 ; U2.4@285.69,311.33 cw(c304.32,311.33) 291.15,324.51 ; C8.1@332.15,323.65 ccw(c315.62,307.11) 315.62,330.5 ccw(c315.62,353.88) C8.1@332.15,337.34
NetC9_1: C9.1 U3.4 | length 65
  Top Layer w25: C9.1@440.5,1089 440.5,1145.85 U3.4@446.24,1151.6
NetC13_1: C13.1 U4.10 | length 105.3
  Top Layer w12: C13.1@689.67,1325.14 cw(c666.75,1302.23) 699.16,1302.23 ; C13.1@696.56,1326.16 699.16,1323.57 U4.10@699.16,1258.92 ; 699.16,1314.77 cw(c713.82,1314.77) C13.1@703.45,1325.14
NetC14_2: C14.2 U4.20 | length 181.8
  Top Layer w12: C14.2@564,1066.44 666.44,1066.44 679.47,1079.47 U4.20@679.47,1103.41 ; C14.2@572.86,1059.55 cw(c589.5,1042.91) 589.5,1066.44 cw(c589.5,1089.97) C14.2@572.86,1073.33
NetCONN1_3: CONN1.3 FIL3.1 | length 140.4
  Top Layer w10: CONN1.3@201.84,759.79 259.79,759.79 283.69,783.69 FIL3.1@306.52,783.69 ; CONN1.3@225.35,754.97 cw(c236.98,743.34) 236.98,759.79 cw(c236.98,776.23) CONN1.3@225.35,764.6
NetCONN1_4: CONN1.4 FIL3.3 | length 140.4
  Top Layer w10: CONN1.4@201.84,720.42 260.42,720.42 284.32,744.32 FIL3.3@306.52,744.32 ; CONN1.4@225.35,715.6 cw(c236.98,703.97) 236.98,720.42 cw(c236.98,736.86) CONN1.4@225.35,725.23
NetCONN1_5: CONN1.5 FIL2.1 | length 137.8
  Top Layer w10: CONN1.5@201.84,681.05 261.05,681.05 278.69,698.69 FIL2.1@306.52,698.69 ; CONN1.5@225.35,676.23 cw(c236.98,664.6) 236.98,681.05 cw(c236.98,697.49) CONN1.5@225.35,685.86
NetCONN1_6: CONN1.6 FIL2.3 | length 137.8
  Top Layer w10: CONN1.6@201.84,641.68 256.68,641.68 274.32,659.32 FIL2.3@306.52,659.32 ; CONN1.6@225.35,636.86 cw(c236.98,625.23) 236.98,641.68 cw(c236.98,658.12) CONN1.6@225.35,646.49
NetCONN1_7: CONN1.7 FIL1.1 | length 864.3
  Top Layer w10: CONN1.7@201.84,602.31 235.69,602.31 ; CONN1.7@219.55,605.34 cw(c224.8,589.23) 236.79,601.21 ; CONN1.7@222.65,595.83 cw(c230.47,571.85) 248.31,589.69 ; CONN1.7@225.63,597.79 cw(c235.69,588.85) 235.69,602.31 ; CONN1.7@225.63,606.83 ccw(c235.69,615.76) 235.69,602.31 ; FIL1.1@291.52,948.69 252.5,948.69 245.18,956 181,956 131.69,906.69 131.69,847.03 84,799.34 84,614 164,534 239,534 248.31,543.31 248.31,589.69 ; 235.69,602.31 248.31,589.69
NetCONN1_8: CONN1.8 FIL1.3 | length 574.3
  Top Layer w10: CONN1.8@178.32,558.12 ccw(c166.69,546.49) 166.69,562.94 ccw(c166.69,579.38) CONN1.8@178.32,567.75 ; CONN1.8@201.84,562.94 165.06,562.94 104.53,623.47 104.53,794.41 149.69,839.58 149.69,874.69 177,902 245.18,902 252.5,909.32 FIL1.3@291.52,909.32
NetCONN2_4: CONN2.4 R10.2 U6.2 | length 346.7
  Top Layer w10: CONN2.4@1014.97,225.35 ccw(c1005.24,235.08) 1019,235.08 ; U6.2@1017.66,320.34 cw(c1009.61,312.29) 1021,312.29 ; 1019,238.88 ccw(c1038.13,238.88) CONN2.4@1024.6,225.35 ; U6.2@1019,327.58 1021,325.58 1021,305.18 1026,300.18 1026,277.82 1019,270.82 1019,202.62 CONN2.4@1019.79,201.84 1119.63,201.84 R10.2@1124,197.47 ; CONN2.4@1024.6,197.02 cw(c1036.23,185.39) 1036.23,201.84 cw(c1036.23,218.28) CONN2.4@1024.6,206.65 ; 1083.19,201.84 cw(c1083.19,166.69) R10.2@1108.04,191.54 ; 1089.47,201.84 ccw(c1089.47,228.09) R10.2@1108.04,209.53
NetD2_1: D2.1 R1.2 | length 131
  Top Layer w20: D2.1@125.5,1009 R1.2@190.53,1009 ; D2.1@132.35,1002.15 cw(c148.88,985.62) 148.88,1009 cw(c148.88,1032.38) D2.1@132.35,1015.85 ; R1.2@185.08,1003.54 ccw(c171.91,990.37) 171.91,1009 ccw(c171.91,1027.63) R1.2@185.08,1014.46
NetD5_1: D5.1 R9.1 | length 131
  Top Layer w20: D5.1@125.5,1089 R9.1@190.53,1089 ; D5.1@132.35,1082.15 cw(c148.88,1065.62) 148.88,1089 cw(c148.88,1112.38) D5.1@132.35,1095.85 ; R9.1@185.08,1083.54 ccw(c171.91,1070.37) 171.91,1089 ccw(c171.91,1107.63) R9.1@185.08,1094.46
NetU1_26: U1.26 U9.6 | length 350.9
  Top Layer w10: U9.6@573.2,344.18 ccw(c561.57,332.56) 561.57,349 ccw(c561.57,365.44) U9.6@573.2,353.82 ; U9.6@609.51,349 554,349 535.2,367.8 535.2,425.2 569,459 629,459 645.42,475.42 U1.26@645.42,514.55 ; 639.44,469.44 ccw(c625.53,483.35) U1.26@645.2,483.35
